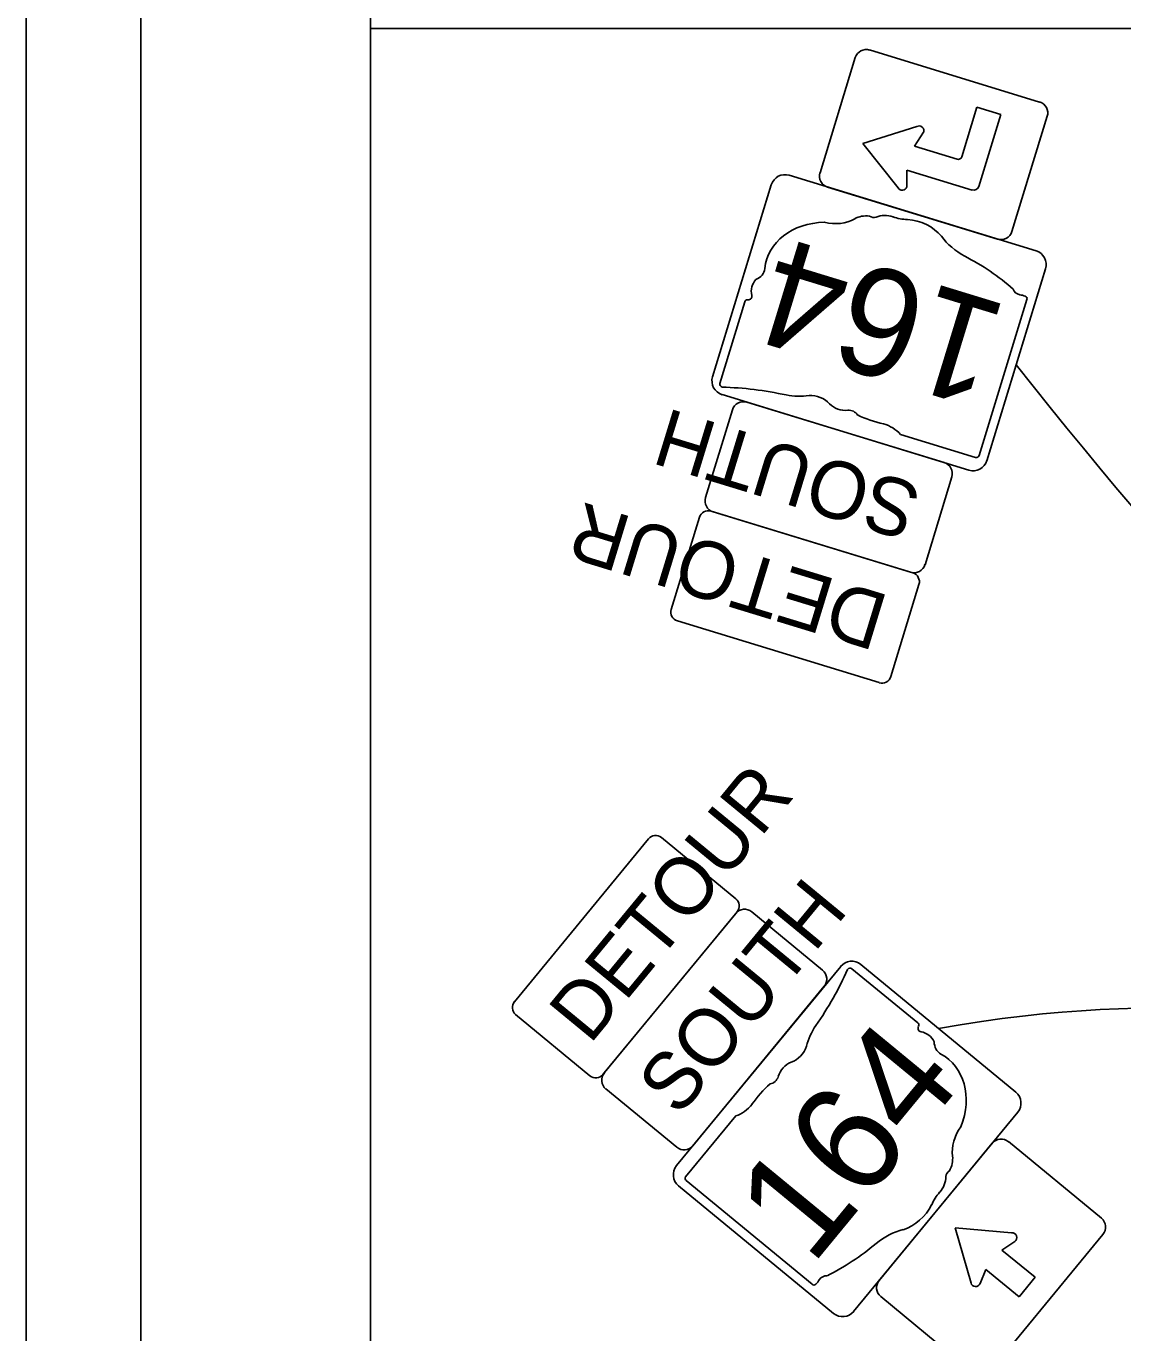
# Model space of a CAD drawing. Extents: x -202 to 1556, y 0 to 676.
# Drawn here: x 0 to 95.6, y 106.3 to 220.2 of the extents above; entities that cross this region are included whole.
import ezdxf

# ---------------------------------------------------------------- set-up
doc = ezdxf.new("R2010")
doc.units = 0
for name, color, linetype in [('GM_X_Minor_Lake', 7, 'Continuous'), ('GM_X_Minor_River_Text', 7, 'Continuous'), ('SH_Border', 7, 'Continuous'), ('SH_Cut_Line', 7, 'Continuous'), ('SH_Data', 7, 'Continuous')]:
    doc.layers.add(name, color=color, linetype=linetype)

msp = doc.modelspace()

# ---------------------------------------------------------------- linework, layer by layer
at = {"layer": 'GM_X_Minor_Lake'}
for p, q in [((88.33, 213.59), (73.51, 218.13)), ((72.26, 217.47), (69.19, 207.43)), ((81.54, 208.81), (82.87, 213.14)), ((82.87, 213.14), (84.96, 212.5)), ((84.96, 212.5), (83.04, 206.23)), ((85.92, 202.31), (88.99, 212.35)), ((72.91, 209.98), (77.63, 211.46)), ((78.22, 210.97), (77.41, 209.75)), ((75.99, 206.11), (72.91, 209.98)), ((77.41, 209.75), (81.15, 208.6)), ((76.77, 207.65), (76.76, 206.19)), ((82.45, 205.92), (76.77, 207.65)), ((69.85, 206.18), (84.67, 201.64)), ((82.45, 205.92), (82.45, 205.92)), ((62.64, 196.17), (60.46, 189.05)), ((62.64, 196.17), (62.64, 196.17)), ((83.05, 182.76), (87.21, 196.37)), ((62.8, 187.42), (80.02, 182.15)), ((59.21, 179.11), (61.55, 186.76)), ((76.19, 184.61), (82.75, 182.6)), ((80.68, 180.9), (78.34, 173.25)), ((77.09, 172.59), (59.88, 177.86)), ((50.39, 128.95), (61.84, 142.85)), ((63.24, 142.98), (69.42, 137.9)), ((77.71, 133.3), (71.96, 138.03)), ((69.56, 136.49), (58.11, 122.59)), ((77.7, 133.3), (77.71, 133.3)), ((56.71, 122.46), (50.53, 127.54)), ((61.84, 125.19), (57.48, 119.89)), ((74.35, 110.85), (84.2, 122.81)), ((85.61, 122.95), (93.71, 116.27)), ((57.52, 119.56), (68.51, 110.51)), ((82.35, 110.61), (80.96, 115.44)), ((80.96, 115.44), (85.89, 115)), ((93.85, 114.86), (84, 102.9)), ((86.16, 114.24), (85.03, 113.5)), ((85.03, 113.5), (87.93, 111.12)), ((83.64, 111.81), (83.14, 110.57)), ((86.54, 109.43), (83.64, 111.81)), ((87.93, 111.12), (86.54, 109.43)), ((82.59, 102.76), (74.48, 109.44))]:
    msp.add_line(p, q, dxfattribs=at)
for points in [[(59.82, 189.64), (64.94, 206.37)], [(66.5, 207.2), (88.02, 200.62)], [(88.85, 199.06), (83.73, 182.32)], [(82.17, 181.49), (60.65, 188.08)], [(77.28, 172.53), (59.69, 177.92)], [(58.69, 177.39), (56.23, 169.35)], [(75.35, 163.5), (77.81, 171.53)], [(56.76, 168.35), (74.35, 162.97)], [(54.24, 149.36), (42.55, 135.15)], [(61.86, 144.13), (55.37, 149.47)], [(50.27, 128.8), (61.96, 143)], [(56.68, 120.86), (70.99, 138.23)], [(72.75, 138.4), (86.26, 127.27)], [(42.66, 134.03), (49.14, 128.69)], [(86.43, 125.51), (72.12, 108.14)], [(70.36, 107.97), (56.85, 119.1)]]:
    msp.add_lwpolyline(points, dxfattribs=at)
for centre, radius, start, end in [((73.22, 217.17), 1, 72.9855, 162.9855), ((88.04, 212.64), 1, 342.9855, 72.9855), ((77.83, 211.09), 0.417, 342.9838, 117.9853), ((81.24, 208.9), 0.312, 252.9855, 342.9855), ((70.14, 207.13), 1, 162.9855, 252.9855), ((66.14, 206.01), 1.25, 72.9855, 162.9855), ((82.59, 206.37), 0.469, 252.9855, 342.9855), ((76.36, 206.31), 0.417, 207.9856, 342.9838), ((84.96, 202.6), 1, 252.9855, 342.9855), ((87.65, 199.42), 1.25, 342.9855, 72.9855), ((61.02, 189.27), 1.25, 162.9855, 252.9855), ((62.51, 186.46), 1, 72.9855, 162.9855), ((82.53, 182.69), 1.25, 252.9855, 342.9855), ((79.72, 181.2), 1, 342.9855, 72.9855), ((60.17, 178.81), 1, 162.9855, 252.9855), ((59.45, 177.15), 0.8, 72.9855, 162.9855), ((77.38, 173.55), 1, 252.9855, 342.9855), ((77.05, 171.77), 0.8, 342.9855, 72.9855), ((56.99, 169.12), 0.8, 162.9855, 252.9855), ((74.59, 163.73), 0.8, 252.9855, 342.9855), ((54.86, 148.85), 0.8, 50.5279, 140.5279), ((61.35, 143.51), 0.8, 320.5279, 50.5279), ((62.61, 142.21), 1, 50.5279, 140.5279), ((68.78, 137.12), 1, 320.5279, 50.5279), ((71.95, 137.43), 1.25, 50.5279, 140.5279), ((43.17, 134.65), 0.8, 140.5279, 230.5279), ((49.65, 129.31), 0.8, 230.5279, 320.5279), ((51.17, 128.31), 1, 140.5279, 230.5279), ((85.46, 126.31), 1.25, 320.5279, 50.5279), ((84.97, 122.17), 1, 50.5279, 140.5279), ((57.34, 123.23), 1, 230.5279, 320.5279), ((57.65, 120.06), 1.25, 140.5279, 230.5279), ((93.08, 115.5), 1, 320.5279, 50.5279), ((85.93, 114.59), 0.417, 303.3233, 95.5374), ((75.12, 110.21), 1, 140.5279, 230.5279), ((82.75, 110.73), 0.417, 195.9391, 337.7325), ((71.16, 108.94), 1.25, 230.5279, 320.5279)]:
    msp.add_arc(centre, radius, start, end, dxfattribs=at)
for centre, major_axis, start_param, end_param in [((70.48, 198.02), (-5.94, 1.82), 5.101752, 6.440018), ((70.11, 205.78), (-3.26, 1), 1.647645, 2.488434), ((73.47, 202.02), (-1.92, 0.59), 4.937069, 5.64225), ((73.83, 203.96), (-0.511, 0.156), 1.147584, 2.315152), ((75.07, 202.14), (-1.82, 0.56), 4.691044, 5.507374), ((76.44, 205.75), (-2.8, 0.86), 1.495662, 1.94098), ((76.97, 200.44), (-3.41, 1.04), 4.026481, 4.996735), ((84.39, 203.92), (-5.37, 1.64), 0.823519, 1.323587), ((73.9, 187.93), (-17.16, 5.25), 4.195997, 4.488961), ((62.66, 199.42), (-1.69, 0.52), 2.387724, 3.262537), ((65.59, 196.82), (-2.32, 0.71), 5.934695, 6.695948), ((86.74, 197.37), (-0.721, 0.221), 0.519207, 1.627899), ((62.91, 196.12), (-0.267, 0.082), 5.05454, 6.418171), ((62.86, 196.67), (-0.386, 0.118), 1.883978, 3.671073), ((86.5, 195.1), (-2, 0.61), 4.665946, 4.897461), ((86.96, 196.48), (-0.262, 0.08), 3.00124, 4.508301), ((60.7, 188.95), (-0.249, 0.076), 6.141152, 7.989035), ((62.87, 168.39), (-23.77, 7.27), 4.814394, 5.042369), ((66.79, 192.03), (-4.78, 1.46), 1.699011, 2.107814), ((68.59, 186.44), (-1.82, 0.56), 4.081561, 5.145723), ((71.2, 188), (-1.51, 0.46), 0.950623, 2.079405), ((71.78, 186.1), (-0.727, 0.222), 3.836095, 5.185415), ((76.13, 192.98), (-9.04, 2.77), 1.404758, 1.657858), ((74.15, 183.51), (-2.52, 0.77), 4.042523, 4.731795), ((82.78, 182.81), (-0.26, 0.079), 1.712693, 3.28349), ((51.95, 143.7), (15.8, 19.19), 4.814394, 5.042369), ((71.77, 137.85), (0.166, 0.201), 6.141152, 7.989035), ((72.29, 131.05), (3.18, 3.86), 1.699011, 2.107814), ((77.55, 133.07), (0.178, 0.216), 5.05454, 6.418171), ((78.09, 132.9), (0.257, 0.312), 1.883978, 3.671073), ((77.18, 130.32), (1.54, 1.87), 5.934695, 6.695948), ((66.44, 131.52), (1.21, 1.47), 4.081561, 5.145723), ((80.7, 132.04), (1.12, 1.36), 2.387724, 3.262537), ((76.42, 125.35), (3.95, 4.8), 5.101752, 6.440018), ((66.89, 128.51), (1, 1.22), 0.950623, 2.079405), ((69.6, 122.05), (6.01, 7.3), 1.404758, 1.657858), ((64.91, 128.69), (0.483, 0.586), 3.836095, 5.185415), ((61.61, 127.5), (1.67, 2.03), 4.042523, 4.731795), ((83.73, 122.72), (2.16, 2.63), 1.647645, 2.488434), ((78.97, 121.05), (1.28, 1.55), 4.937069, 5.64225), ((57.67, 119.79), (0.173, 0.21), 1.712693, 3.28349), ((78.47, 119.53), (1.21, 1.47), 4.691044, 5.507374), ((80.63, 119.98), (0.34, 0.413), 1.147584, 2.315152), ((81.28, 116.88), (1.86, 2.26), 1.495662, 1.94098), ((76.17, 118.42), (2.27, 2.75), 4.026481, 4.996735), ((76.56, 110.24), (3.57, 4.33), 0.823519, 1.323587), ((65.79, 126.04), (11.41, 13.86), 4.195997, 4.488961), ((68.7, 110.7), (0.174, 0.211), 3.00124, 4.508301), ((67.61, 111.66), (1.33, 1.61), 4.665946, 4.897461), ((69.61, 110.56), (0.479, 0.582), 0.519207, 1.627899)]:
    msp.add_ellipse(centre, major_axis=major_axis, ratio=0.8, start_param=start_param, end_param=end_param, dxfattribs=at)
at = {"layer": 'GM_X_Minor_River_Text'}
msp.add_line((30, 220), (640, 220), dxfattribs=at)
at = {"layer": 'SH_Border'}
for points in [[(10, 430), (30, 430), (30, 10), (10, 10)], [(30, 430), (670, 430), (670, 10), (30, 10)]]:
    msp.add_lwpolyline(points, close=True, dxfattribs=at)
at = {"layer": 'SH_Cut_Line'}
msp.add_lwpolyline([(0, 0), (680, 0), (680, 440), (0, 440)], close=True, dxfattribs=at)
at = {"layer": 'SH_Data'}
for points in [[(86.29, 190.69), (102.24, 170.36), (128.97, 144.07), (149.56, 133.27), (172.62, 130.54), (191.35, 132)], [(79.52, 132.82), (99.83, 136.42), (127.65, 131.33), (152.16, 125.11), (172.51, 121.38), (186.79, 122.16)], [(72.68, 92.44), (98.67, 92.22), (111.17, 94.55), (131, 99.43), (168.35, 118.15), (182.67, 118.56)]]:
    msp.add_open_spline(points, degree=3, dxfattribs=at)

# ---------------------------------------------------------------- texts
at = {"layer": 'GM_X_Minor_Lake'}
for s, height, rotation, p in [('164', 9.375, 162.9855, (85.82, 195.75)), ('SOUTH', 5, 162.9855, (78.25, 180.08)), ('DETOUR', 5, 162.9855, (75.37, 170.5)), ('DETOUR', 5, 50.5279, (49.12, 131.34)), ('SOUTH', 5, 50.5279, (56.87, 125.02)), ('164', 9.375, 50.5279, (68.46, 112.04))]:
    msp.add_text(s, height=height, rotation=rotation, dxfattribs=at).set_placement(p)

doc.saveas('drawing.dxf')
